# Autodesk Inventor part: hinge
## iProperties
Author: Administrator
Created: 2001-01
Part Number: hinge
Document SubType Name: Modeling
Designer: Administrator
Control State: 0
Master: False
Checked Out: False
PropertySet Name: Design Tracking Control
Shininess: 0.0
PropertySet Name: _Private Model Information
Density: 0.0
Volumn: 0.0
Area: 0.0
PropertySet Name: Model Information
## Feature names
1. Extrusion1
2. Hole1
3. Hole2
